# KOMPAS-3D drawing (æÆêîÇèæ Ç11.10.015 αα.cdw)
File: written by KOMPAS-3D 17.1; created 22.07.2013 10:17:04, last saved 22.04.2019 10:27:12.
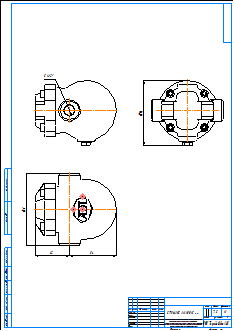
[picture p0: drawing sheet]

Sheet 1: A2, portrait

Title block, sheet 1: name: СТИМАКС А11.10.015 рр; material: Внимание! Данный продукт является объектом авторского права ООО «Торговый Дом АДЛ». / Запрещается изменение, копирование, распространение / (в том числе путем копирования на другие сайты и ресурсы в Интернете) / или любое иное использование информации и объектов без предварительного / согласия правообладателя (ООО «Торговый Дом АДЛ»).; mass: 7,5; sheets: 1; organisation: ООО "Торговый дом АДЛ"; sheet format: A2; stored path: \\adlc.lan\data\АДЛ_ПКД\3D-модели\ADL production\Конденсатоотводчики СТИМАКС\Поплавковые\Серия А11\KOMPAS 2D\СТИМАКС А11.10.015 рр.cdw

Views: Вид 1
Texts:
  Klimkovich
  ADL
Dimensions and other numbers on the sheet: 1:1; 1; 7,5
